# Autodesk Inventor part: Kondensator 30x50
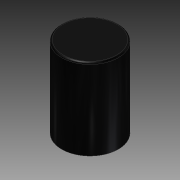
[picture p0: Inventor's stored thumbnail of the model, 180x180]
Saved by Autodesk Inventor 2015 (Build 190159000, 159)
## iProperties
Created: 2012-08
Part Number: Kondensator 30x50
Material: PC/ABS-Kunststoff
Document SubType Name: Modeling
Designer: rYan
Density: 1.493 g/cm^3
Mass: 52.7748 g
Surface Area: 61.3547 cm^2
Volume: 35.3481 cm^3
Appearance: Glänzend - schwarz
Author: rYan
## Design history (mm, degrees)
sketch "Skizze1"
  geometry: C1 r 17.5 at (0, 0); 1 further point
  constraints: 1 centre point, 1 coincident
  dimensions: "d0" = 35 diameter of C1
extrude "Extrusion1" new body sketch "Skizze1" distance "d1" = 50; taper "d2" = 0 deg
fillet "Rundung1" dims "d3" = 1
sketch "Skizze2"
  geometry: L1 (-24.5, 0)-(24.5, 0) reference; L2 (0, -24.5)-(0, 24.5) reference; C1 r 1 at (-5, 0); C2 r 1 at (5, 0); 2 further points
  constraints: 2 centre point, 2 coincident, 2 point on line, 1 symmetric about line, 1 other
  dimensions: "d4" = 10 distance of point (5, 0) point (-5, 0); "d5" = 2 diameter of C1
extrude "Extrusion2" join sketch "Skizze2" distance "d6" = 4; taper "d7" = 0 deg
workplane "Arbeitsebene1"
node "Volumenkörper1"
other parameters: "d8" = 0
